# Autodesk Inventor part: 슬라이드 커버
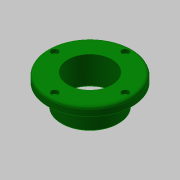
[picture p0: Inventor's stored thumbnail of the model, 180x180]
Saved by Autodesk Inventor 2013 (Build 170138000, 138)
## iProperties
Created: 2015-10
Part Number: 슬라이드 커버
Document SubType Name: Modeling
Designer: mdu
Density: 7.86 g/cm^3
Material: 알루미늄 6061
Mass: 598.523 g
Surface Area: 229.996 cm^2
Volume: 76.148 cm^3
Author: mdu
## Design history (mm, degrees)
sketch "스케치1"
  geometry: C1 r 47.5 at (0, 0); C2 r 32.5 at (0, 0); 1 further point
  constraints: 2 centre point, 2 coincident
  dimensions: "d33" = 95 diameter of C1; "d35" = 65 diameter of C2
extrude "돌출1" new body sketch "스케치1" distance "d0" = 10; taper "d1" = 0 deg
extrude "돌출2" join sketch "스케치1" distance "d2" = 25; taper "d3" = 0 deg
hole "구멍1" diameter "d6" = 50; stored, may be unused: countersink angle "d10" = 90 deg, drill point angle "d12" = 118 deg; dims "d4" = 10, "d5" = 10, "d7" = 6, "d8" = 4, "d9" = 2, "d11" = 8
sketch "스케치2" dims "d36" = 80
  geometry: 4 further points
  constraints: 2 coincident, 2 vertical alignment, 2 other
hole "구멍2" sketch "스케치2" at (0, 40) diameter "d13" = 4.5; stored, may be unused: countersink angle "d17" = 90 deg, drill point angle "d19" = 118 deg; dims "d14" = 6, "d15" = 8, "d16" = 4.4, "d18" = 8
fillet "모깎기1" dims "d23" = 3
chamfer "모따기1" distance "d24" = 1; stored, may be unused: second distance "d25" = 2, angle "d26" = 45 deg
sketch "스케치3"
  geometry: C1 r 25 at (0, 0); C2 r 30 at (0, 0); C3 r 26 at (0, 0) reference; 1 further point
  constraints: 2 centre point, 2 coincident
  dimensions: "d27" = 60 diameter of C2
extrude "돌출3" cut sketch "스케치3" distance "d28" = 3; taper "d29" = 0 deg
chamfer "모따기2" distance "d30" = 1; stored, may be unused: second distance "d31" = 2, angle "d32" = 45 deg
node "솔리드1"
pattern_circular "원형 패턴1" dims angle "d21" = 360 deg
